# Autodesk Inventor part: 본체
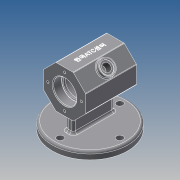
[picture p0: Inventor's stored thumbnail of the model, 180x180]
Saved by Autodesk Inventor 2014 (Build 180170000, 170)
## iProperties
Created: 2021-02
Part Number: 본체
Material: 일반
Document SubType Name: Modeling
Designer: kbl
Density: 1 g/cm^3
Appearance: 기본값
Mass: 206.204 g
Surface Area: 509.677 cm^2
Volume: 206.204 cm^3
Author: kbl
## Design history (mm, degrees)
sketch "스케치1"
  geometry: L1 (12.012, 29)-(29, 12.012); L2 (29, 12.012)-(29, -12.012); L3 (29, -12.012)-(12.012, -29); L4 (12.012, -29)-(-12.012, -29); L5 (-12.012, -29)-(-29, -12.012); L6 (-29, -12.012)-(-29, 12.012); L7 (-29, 12.012)-(-12.012, 29); L8 (-12.012, 29)-(12.012, 29); C1 r 29 at (0, 0); 2 further points
  constraints: 16 end point, 2 coincident, 1 centre point, 1 horizontal, 1 tangent, 17 other
  dimensions: "d0" = 58 diameter of C1
extrude "돌출1" new body sketch "스케치1" stored distance "d1" = 70; taper "d2" = 0 deg
sketch "스케치2"
  geometry: L1 (29, 35)-(12.012, 35) reference; L2 (12.012, 35)-(-12.012, 35) reference; L3 (-12.012, 35)-(-29, 35) reference; L4 (12.012, -35)-(29, -35) reference; L5 (-12.012, -35)-(12.012, -35) reference; L6 (-29, -35)-(-12.012, -35) reference; L7 (0, 35)-(0, -35); L8 (16, 35)-(16, 23.3); L9 (15.7, 23)-(14, 23); L10 (14, 23)-(14, 20); L11 (14, 20)-(19, 20); L12 (22, 17)-(22, -17); L13 (19, -20)-(14, -20); L14 (14, -20)-(14, -23); L15 (14, -23)-(15.7, -23); L16 (16, -23.3)-(16, -35); A1 r 3 centre (19, -17) between (19, -20) and (22, -17); A2 r 3 centre (19, 17) between (22, 17) and (19, 20); A3 r 0.3 centre (15.7, -23.3) between (16, -23.3) and (15.7, -23); A4 r 0.3 centre (15.7, 23.3) between (15.7, 23) and (16, 23.3); 5 further points
  constraints: 20 end point, 10 point on line, 8 point on circle, 8 tangent, 7 parallel, 4 centre point, 2 collinear, 2 equal radius, 2 midpoint, 1 perpendicular
  dimensions: "d3" = 28 diameter of L10 L7; "d4" = 28 diameter of L14 L7; "d5" = 32 diameter of L16 L7; "d6" = 32 diameter of L8 L7; "d7" = 44 diameter of L12 L7; "d9" = 12 distance of point (16, -23) L16.end; "d11" = 12 distance of L8.start point (16, 23); "d13" = 40 distance of point (22, 20) point (22, -20); "d15" = 3 radius of A1; "d40" = 0.3 radius of A3
revolve "회전1" sketch "스케치2" stored, may be unused: angle "d14" = 90 deg
chamfer "모따기1" distance "d16" = 1; stored, may be unused: second distance "d17" = 2, angle "d18" = 45 deg
sketch "스케치3"
  geometry: C1 r 17 at (0, 0) reference; 1 further point
  constraints: 1 vertical alignment
  dimensions: "d19" = 23 distance of C1.centre point (0, 23)
hole "구멍1" sketch "스케치3" at (0, 23) diameter "d20" = 3.242; stored, may be unused: countersink angle "d24" = 90 deg, drill point angle "d26" = 118 deg; dims "d21" = 8, "d22" = 4, "d23" = 2, "d25" = 10
node "작업 평면1"
sketch "스케치4"
  geometry: C1 r 52 at (0, 0); C2 r 4.5 at (0, 41); C3 r 4.5 at (0, -41); C4 r 4.5 at (41, 0); C5 r 4.5 at (-41, 0); A1 r 41 centre (0, 0) between (0, 41) and (0, -41); 1 further point
  constraints: 6 centre point, 4 point on circle, 3 equal radius, 2 coincident, 2 horizontal alignment, 2 vertical alignment
  dimensions: "d31" = 104 diameter of C1; "d32" = 82 diameter of A1; "d33" = 9 diameter of C4
extrude "돌출2" join sketch "스케치4" distance "d34" = 10; taper "d35" = 0 deg
sketch "스케치5"
  geometry: L1 (-5, -28)-(5, -28); L2 (5, -28)-(5, 28); L3 (5, 28)-(-5, 28); L4 (-5, 28)-(-5, -28); L5 (-5, -28)-(5, 28); L6 (5, -28)-(-5, 28); C1 r 52 at (0, 0) reference
  constraints: 12 end point, 2 midpoint, 2 parallel, 1 horizontal, 1 perpendicular
  dimensions: "d36" = 10 distance of L2.end L3.end; "d37" = 56 distance of L1.end L2.end
extrude "돌출3" join sketch "스케치5" stored distance "d38" = 10; taper "d39" = 0 deg
sketch "스케치6"
  geometry: C1 r 10 at (-12.012, 35); 1 further point
  constraints: 1 centre point, 1 coincident
  dimensions: "d41" = 20 diameter of C1
extrude "돌출4" join sketch "스케치6" distance "d42" = 5; taper "d43" = 0 deg
hole "구멍2" diameter "d46" = 16; stored, may be unused: countersink angle "d50" = 90 deg, drill point angle "d52" = 0 deg; dims "d47" = 8, "d48" = 4, "d49" = 2, "d51" = 2, "d55" = 10, "d56" = 10
hole "구멍3" diameter "d57" = 10.917; stored, may be unused: countersink angle "d61" = 90 deg, drill point angle "d63" = 118 deg; dims "d58" = 8, "d59" = 4, "d60" = 2, "d62" = 2, "d66" = 10, "d67" = 10
chamfer "모따기2" distance "d64" = 1; stored, may be unused: second distance "d65" = 2, angle "d68" = 45 deg
sketch "스케치7"
  geometry: L1 (24.024, 0)-(0, 0) reference; L2 (-16.988, 0)-(-16.988, 70) reference; 2 further points
  constraints: 1 other
  dimensions: "d69" = 35 distance from line of point (12.012, 35) L1; "d70" = 29 distance from line of point (12.012, 35) L2
feature "엠보싱1" sketch "스케치7" dims "d0" = 58, "d71" = 0.5, "d72" = 0
fillet "모깎기1" dims "d73" = 1, "d74" = 3
fillet "모깎기2" dims "d75" = 3
node "솔리드1"
pattern_circular "원형 패턴1" dims angle "d28" = 360 deg
mirror "대칭1"
other parameters: "d30" = -62
